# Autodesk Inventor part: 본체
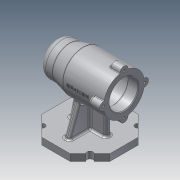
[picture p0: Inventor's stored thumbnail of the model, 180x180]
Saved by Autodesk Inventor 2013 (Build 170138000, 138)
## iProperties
Created: 2021-01
Part Number: 본체
Material: 알루미늄 6061
Document SubType Name: Modeling
Designer: a
Density: 2.71 g/cm^3
Mass: 631.974 g
Surface Area: 614.666 cm^2
Volume: 233.201 cm^3
Author: a
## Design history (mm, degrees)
sketch "스케치1"
  geometry: L1 (-50, 0)-(50, 0); L2 (50, 0)-(50, 30); L3 (50, 30)-(-10, 30); L4 (-10, 30)-(-30, 25); L5 (-30, 25)-(-50, 25); L6 (-50, 25)-(-50, 0); L7 (50, 21)-(35, 21); L8 (35, 21)-(35, 24); L9 (35, 24)-(-7, 24); L10 (-7, 24)-(-7, 21); L11 (-7, 21)-(-19, 21); L12 (-19, 21)-(-19, 17.5); L13 (-19, 17.5)-(-37, 17.5); L14 (-37, 17.5)-(-37, 16); L15 (-37, 16)-(-41, 16); L16 (-41, 16)-(-41, 10.5); L17 (-41, 10.5)-(-44, 10.5); L18 (-44, 10.5)-(-44, 0); 2 further points
  constraints: 36 end point, 10 parallel, 5 perpendicular, 2 point on line, 1 coincident, 1 collinear, 1 horizontal, 1 midpoint
  dimensions: "d0" = 100 distance of L1.start L1.end; "d1" = 40 horizontal distance of L3.end L1.start; "d2" = 20 horizontal distance of L1.start L4.end; "d3" = 60 diameter of L3 L1; "d4" = 50 diameter of L5 L1; "d5" = 42 diameter of L7 L1; "d6" = 42 diameter of L11 L1; "d7" = 48 diameter of L9 L1; "d8" = 35 diameter of L13 L1; "d9" = 32 diameter of L15 L1; "d10" = 21 diameter of L17 L1; "d11" = 15 distance of L7.start L7.end; "d12" = 42 distance of L8.end L9.end; "d13" = 18 distance of L12.end L13.end; "d14" = 12 distance of L10.end L11.end; "d15" = 4 distance of L14.end L15.end; "d16" = 3 distance of L16.end L17.end
revolve "회전1" sketch "스케치1" stored, may be unused: angle "d17" = 90 deg
fillet "모깎기1" dims "d18" = 3
fillet "모깎기2" dims "d19" = 0.3
chamfer "모따기1" distance "d20" = 1; stored, may be unused: second distance "d21" = 2, angle "d22" = 45 deg
fillet "모깎기3" dims "d23" = 10
node "작업 평면1"
sketch "스케치2"
  geometry: L1 (-20.711, -50)-(-50, -20.711); L2 (-50, -20.711)-(-50, 20.711); L3 (-50, 20.711)-(-20.711, 50); L4 (-20.711, 50)-(20.711, 50); L5 (20.711, 50)-(50, 20.711); L6 (50, 20.711)-(50, -20.711); L7 (50, -20.711)-(20.711, -50); L8 (20.711, -50)-(-20.711, -50); 3 further points
  constraints: 16 end point, 1 coincident, 1 midpoint, 1 vertical alignment, 17 other
  dimensions: "d25" = 50 distance from line of L2 point (0, 0)
extrude "돌출1" join sketch "스케치2" distance "d26" = 10; taper "d27" = 0 deg
sketch "스케치3"
  geometry: L1 (20.711, 50)-(-20.711, 50) reference; L2 (-20.711, 50)-(-50, 20.711) reference; L3 (20.711, -50)-(50, -20.711) reference; L4 (0, 0)-(0, 50); L5 (0, 0)-(-35.355, 35.355); C1 r 4.5 at (-35.355, 35.355)
  constraints: 4 end point, 2 midpoint, 1 centre point, 1 coincident, 1 perpendicular
  dimensions: "d29" = 9 diameter of C1
extrude "돌출2" cut sketch "스케치3" stored distance "d30" = 10; taper "d31" = 0 deg
sketch "스케치4"
  geometry: L1 (27, -4)-(-27, -4); L2 (-27, -4)-(-27, 4); L3 (-27, 4)-(27, 4); L4 (27, 4)-(27, -4); L5 (27, -4)-(-27, 4); L6 (-27, -4)-(27, 4); 1 further point
  constraints: 12 end point, 2 midpoint, 2 parallel, 1 horizontal, 1 perpendicular
  dimensions: "d35" = 54 distance of L2.end L3.end; "d36" = 8 distance of L3.end L1.start
extrude "돌출3" join sketch "스케치4" stored distance "d37" = 10; taper "d38" = 0 deg
feature "면 기울기1" dims angle "d39" = 11 deg
sketch "스케치6"
  geometry: L1 (-75, -50)-(-75, 50) reference; L2 (-75, 50)-(-65, 50) reference; L3 (-65, 50)-(-65, 4) reference; L4 (-65, 4)-(-29.732, 4) reference; L5 (-29.732, -4)-(-65, -4) reference; L6 (-65, -4)-(-65, -50) reference; L7 (-65, -50)-(-75, -50) reference; L8 (-22.707, 19.606)-(-65, 35); C1 r 24 at (0, 0) reference; A1 r 30 centre (0, 0) between (-29.732, -4) and (-29.732, 4) reference; 1 further point
  constraints: 2 end point, 1 point on circle, 1 point on line
  dimensions: "d40" = 110 deg angle of L3 L8; "d41" = 15 distance from line of L8.end L2
feature "리브1" sketch "스케치6" dims "d42" = 1, "d43" = 8, "d44" = 0, "d45" = 0, "d46" = 1, "d47" = 1
sketch "스케치7"
  geometry: C1 r 6 at (0, 30); 1 further point
  constraints: 2 vertical alignment, 1 centre point, 1 other
  dimensions: "d48" = 12 diameter of C1
extrude "돌출4" join sketch "스케치7" distance "d49" = 16; taper "d50" = 0 deg
fillet "모깎기4" dims "d51" = 3
fillet "모깎기5" dims "d52" = 1
sketch "스케치8"
  geometry: A1 r 6 centre (0, 0) between (5.998, 0.171) and (-5.998, 0.171) reference; 1 further point
  constraints: 1 coincident
hole "구멍1" sketch "스케치8" at (0, 0) diameter "d53" = 3.242; stored, may be unused: countersink angle "d57" = 90 deg, drill point angle "d59" = 118 deg; dims "d54" = 8, "d55" = 4, "d56" = 2, "d58" = 10
fillet "모깎기6" dims "d63" = 3
fillet "모깎기7" dims "d64" = 3
fillet "모깎기8" dims "d65" = 3
node "작업 평면2"
sketch "스케치9"
  geometry: L1 (50, 6.771)-(50, 29.226) reference; 2 further points
  constraints: 1 horizontal alignment, 1 other
  dimensions: "d67" = 38 distance from line of L1 point (12, 0)
feature "엠보싱1" sketch "스케치9" dims "d0" = 100, "d1" = 40, "d2" = 20, "d3" = 60, "d4" = 50, "d5" = 42, "d6" = 42, "d7" = 48, "d8" = 35, "d9" = 32, "d10" = 21, "d11" = 15, "d12" = 42, "d13" = 18, "d14" = 12, "d15" = 4, "d16" = 3, "d68" = 0.5, "d69" = 0
node "솔리드1"
pattern_circular "원형 패턴1" dims angle "d33" = 360 deg
mirror "대칭1"
pattern_circular "원형 패턴2" dims "d61" = 360 deg
node "절단 모서리 투영1"
other parameters: "d24" = -75, "d66" = 37.5
